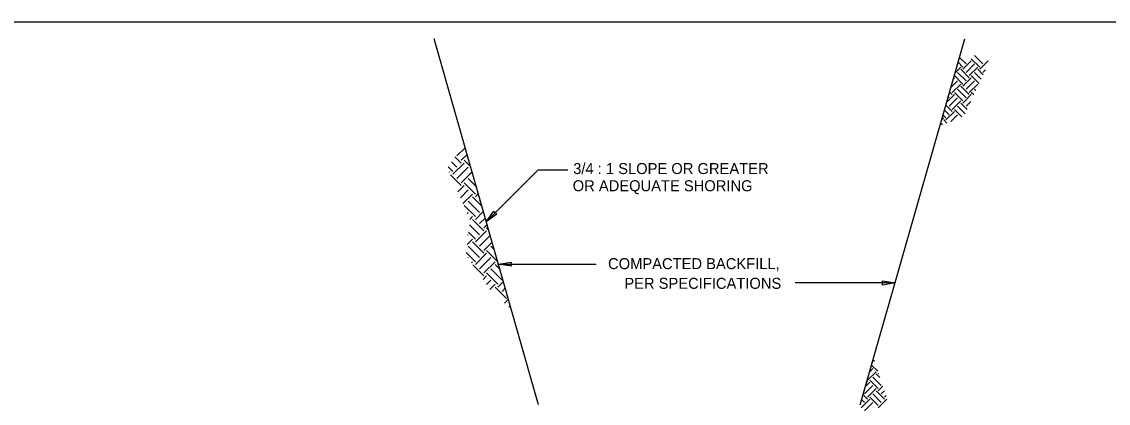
# Model space of a CAD drawing. Extents: x -118779 to -116979, y -104389 to -102939.
# Drawn here: x -117879 to -117287, y -103147 to -102939 of the extents above; entities that cross this region are included whole.
import ezdxf

# ---------------------------------------------------------------- set-up
doc = ezdxf.new("R2010")
doc.units = 0
for name, color, linetype in [('Default', 7, 'Continuous'), ('G-MARK', 7, 'Continuous'), ('G-TEXT', 7, 'Continuous'), ('Misc CnstDet(22)', 7, 'Continuous')]:
    doc.layers.add(name, color=color, linetype=linetype)

msp = doc.modelspace()

# ---------------------------------------------------------------- linework, layer by layer
at = {"layer": 'Default'}
msp.add_lwpolyline([(-118779.39, -102939.25), (-116979.39, -102939.25), (-116979.39, -104389.25), (-118779.39, -104389.25)], close=True, dxfattribs=at)
at = {"layer": 'G-MARK'}
for p, q in [((-117619.43, -103071.54), (-117566.08, -103071.54)), ((-117402.91, -103081.79), (-117457.59, -103081.79))]:
    msp.add_line(p, q, dxfattribs=at)
msp.add_lwpolyline([(-117626.02, -103048.44), (-117597.8, -103020.05), (-117581.62, -103020.05)], dxfattribs=at)
at = {"layer": 'G-TEXT'}
for points in [[(-117620.26, -103044.32), (-117626.02, -103048.44), (-117621.9, -103042.68)], [(-117612.44, -103072.67), (-117619.43, -103071.54), (-117612.44, -103070.37)], [(-117409.87, -103080.66), (-117402.91, -103081.79), (-117409.87, -103082.95)]]:
    msp.add_lwpolyline(points, close=True, dxfattribs=at)
at = {"layer": 'Misc CnstDet(22)'}
for p, q in [((-117597.5, -103148.35), (-117654.5, -102948.55)), ((-117422.06, -103148.35), (-117365.03, -102948.55)), ((-117364.34, -102962.3), (-117367.94, -102958.73)), ((-117366.09, -102965.18), (-117361.46, -102960.55)), ((-117356.87, -102964.01), (-117361.46, -102959.42)), ((-117355.12, -102962.3), (-117359.75, -102957.67)), ((-117356.87, -102965.18), (-117352.24, -102960.55)), ((-117370.34, -102967.1), (-117367.25, -102964.01)), ((-117364.34, -102971.52), (-117368.97, -102966.92)), ((-117366.09, -102964.01), (-117368.69, -102961.41)), ((-117362.63, -102969.8), (-117367.25, -102965.18)), ((-117364.34, -102966.92), (-117359.75, -102962.3)), ((-117362.63, -102968.64), (-117358, -102964.01)), ((-117356.08, -102970.56), (-117359.75, -102966.92)), ((-117354.98, -102968.23), (-117358, -102965.18)), ((-117355.12, -102966.92), (-117353.72, -102965.52)), ((-117372.64, -102975.19), (-117368.97, -102971.52)), ((-117371.23, -102970.35), (-117370.72, -102969.8)), ((-117366.09, -102973.27), (-117370.72, -102968.64)), ((-117366.09, -102974.4), (-117361.46, -102969.8)), ((-117364.34, -102976.14), (-117359.75, -102971.52)), ((-117357.18, -102972.92), (-117361.46, -102968.64)), ((-117371.85, -102979.02), (-117373.32, -102977.58)), ((-117371.85, -102977.86), (-117367.25, -102973.27)), ((-117366.09, -102982.49), (-117370.72, -102977.86)), ((-117364.34, -102980.77), (-117368.97, -102976.14)), ((-117362.63, -102979.02), (-117367.25, -102974.4)), ((-117362.63, -102977.86), (-117358, -102973.27)), ((-117360.09, -102979.23), (-117361.46, -102977.86)), ((-117358.99, -102976.86), (-117359.75, -102976.14)), ((-117357.9, -102974.5), (-117358, -102974.4)), ((-117371.85, -102988.28), (-117375.38, -102984.75)), ((-117374.93, -102983.27), (-117370.72, -102979.02)), ((-117373.6, -102980.77), (-117374.08, -102980.26)), ((-117373.6, -102985.37), (-117368.97, -102980.77)), ((-117371.85, -102987.11), (-117367.25, -102982.49)), ((-117363.76, -102987.11), (-117367.25, -102983.65)), ((-117366.09, -102983.65), (-117361.46, -102979.02)), ((-117364.34, -102985.37), (-117361.74, -102982.76)), ((-117375.31, -102991.74), (-117376.89, -102990.16)), ((-117373.6, -102989.99), (-117376.13, -102987.46)), ((-117375.31, -102992.87), (-117370.72, -102988.28)), ((-117372.67, -102993.69), (-117368.97, -102989.99)), ((-117366.6, -102991.23), (-117370.72, -102987.11)), ((-117364.86, -102989.48), (-117368.97, -102985.37)), ((-117377.26, -102995.55), (-117378.19, -102994.65)), ((-117377.71, -102992.94), (-117376.48, -102991.74)), ((-117374.8, -102994.55), (-117376.48, -102992.87)), ((-117641.99, -103012.51), (-117637.53, -103008.06)), ((-117639.66, -103016.35), (-117643.09, -103012.92)), ((-117639.66, -103014.81), (-117636.5, -103011.66)), ((-117644.28, -103020.98), (-117646.75, -103018.51)), ((-117641.99, -103018.65), (-117644.94, -103015.7)), ((-117644.28, -103022.52), (-117638.12, -103016.35)), ((-117641.99, -103024.82), (-117635.82, -103018.65)), ((-117634.58, -103018.34), (-117638.12, -103014.81)), ((-117646.14, -103021.29), (-117645.83, -103020.98)), ((-117639.66, -103028.66), (-117645.48, -103022.83)), ((-117639.66, -103027.12), (-117633.76, -103021.22)), ((-117631.53, -103029.1), (-117635.82, -103024.82)), ((-117633.35, -103022.66), (-117633.52, -103022.52)), ((-117641.99, -103030.99), (-117641.99, -103030.95)), ((-117641.51, -103032.05), (-117638.12, -103028.66)), ((-117640.14, -103035.27), (-117635.82, -103030.99)), ((-117631.98, -103033.29), (-117638.12, -103027.12)), ((-117638.73, -103038.53), (-117633.52, -103033.29)), ((-117629.65, -103043.29), (-117635.82, -103037.12)), ((-117628.45, -103039.87), (-117633.52, -103034.83)), ((-117631.98, -103034.83), (-117630.37, -103033.22)), ((-117629.65, -103037.12), (-117629.34, -103036.78)), ((-117631.98, -103045.59), (-117638.12, -103039.46)), ((-117636.44, -103043.88), (-117635.82, -103043.29)), ((-117631.98, -103047.13), (-117627.63, -103042.78)), ((-117635.03, -103047.13), (-117633.52, -103045.59)), ((-117627.35, -103053.3), (-117633.52, -103047.13)), ((-117629.65, -103049.43), (-117626.6, -103046.38)), ((-117635.85, -103055.67), (-117635.82, -103055.6)), ((-117631.98, -103057.9), (-117635.72, -103054.16)), ((-117629.65, -103055.6), (-117635.24, -103050.05)), ((-117631.98, -103059.44), (-117625.81, -103053.3)), ((-117627.35, -103051.76), (-117625.57, -103049.98)), ((-117624.75, -103052.79), (-117625.81, -103051.76)), ((-117636.47, -103060.88), (-117633.52, -103057.9)), ((-117629.65, -103067.91), (-117635.82, -103061.77)), ((-117627.35, -103065.61), (-117633.52, -103059.44)), ((-117629.65, -103061.77), (-117623.86, -103055.94)), ((-117627.35, -103064.07), (-117622.83, -103059.54)), ((-117621.7, -103063.59), (-117623.51, -103061.77)), ((-117631.98, -103070.24), (-117636.95, -103065.23)), ((-117631.98, -103071.74), (-117625.81, -103065.61)), ((-117619.85, -103070.03), (-117625.81, -103064.07)), ((-117635.99, -103068.11), (-117635.82, -103067.91)), ((-117634.1, -103070.82), (-117633.52, -103070.24)), ((-117627.35, -103077.91), (-117633.32, -103071.95)), ((-117629.65, -103074.08), (-117623.51, -103067.91)), ((-117627.35, -103076.37), (-117621.18, -103070.24)), ((-117618.61, -103074.35), (-117621.18, -103071.74)), ((-117619.64, -103071.74), (-117619.43, -103071.54)), ((-117627.8, -103079.9), (-117625.81, -103077.91)), ((-117619.64, -103082.54), (-117625.81, -103076.37)), ((-117617.34, -103080.21), (-117623.51, -103074.08)), ((-117625.91, -103082.61), (-117623.51, -103080.21)), ((-117623.99, -103085.35), (-117621.18, -103082.54)), ((-117615.05, -103090.22), (-117621.18, -103084.08)), ((-117619.64, -103084.08), (-117616.69, -103081.1)), ((-117617.34, -103086.38), (-117615.66, -103084.7)), ((-117616.14, -103092.86), (-117613.95, -103090.67)), ((-117615.05, -103088.68), (-117614.63, -103088.3)), ((-117613.71, -103095.05), (-117612.92, -103094.26)), ((-117412.54, -103129.98), (-117415.86, -103126.66)), ((-117414.35, -103124.7), (-117415.11, -103123.95)), ((-117418.02, -103134.85), (-117413.43, -103130.26)), ((-117416.89, -103130.26), (-117415.14, -103128.51)), ((-117411.34, -103133.48), (-117413.43, -103131.39)), ((-117412.26, -103131.39), (-117412.09, -103131.25)), ((-117419.77, -103142.36), (-117415.14, -103137.76)), ((-117419.19, -103138.35), (-117416.89, -103136.01)), ((-117418.02, -103136.01), (-117418.43, -103135.64)), ((-117412.26, -103139.48), (-117416.89, -103134.85)), ((-117410.55, -103137.76), (-117415.14, -103133.14)), ((-117412.26, -103140.64), (-117409.76, -103138.11)), ((-117418.02, -103145.27), (-117420.49, -103142.8)), ((-117418.02, -103144.1), (-117413.43, -103139.48)), ((-117412.26, -103148.73), (-117416.89, -103144.1)), ((-117410.55, -103146.98), (-117415.14, -103142.36)), ((-117408.8, -103145.27), (-117413.43, -103140.64)), ((-117410.55, -103142.36), (-117408.87, -103140.71)), ((-117408.8, -103144.1), (-117407.98, -103143.28)), ((-117421.48, -103149.86), (-117416.89, -103145.27)), ((-117419.77, -103146.98), (-117421.24, -103145.51)), ((-117419.77, -103151.61), (-117415.14, -103146.98)), ((-117412.26, -103149.86), (-117407.63, -103145.27))]:
    msp.add_line(p, q, dxfattribs=at)

# ---------------------------------------------------------------- texts
for s, p in [('3/4 : 1 SLOPE OR GREATER', (-117578.6, -103022.38)), ('OR ADEQUATE SHORING', (-117578.87, -103031.76)), ('COMPACTED BACKFILL,', (-117559.59, -103074.27)), ('PER SPECIFICATIONS', (-117550.71, -103085.01))]:
    msp.add_text(s, height=6, dxfattribs=at).set_placement(p)

doc.saveas('drawing.dxf')
